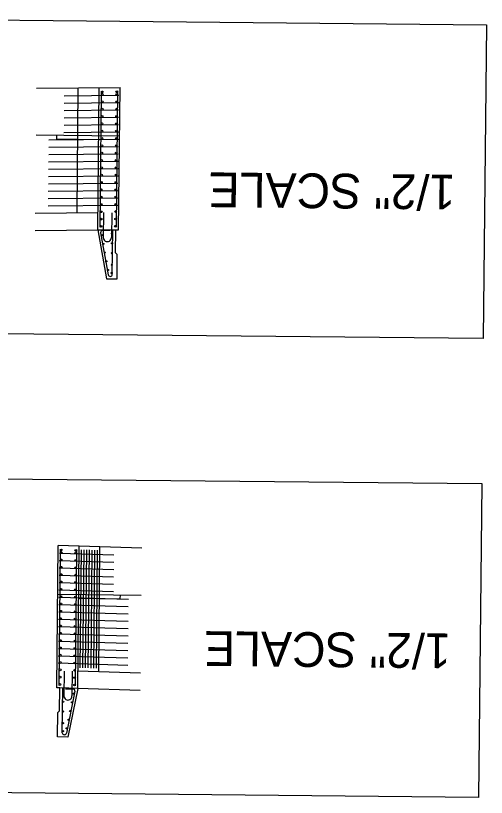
# Model space of a CAD drawing. Extents: x 631918 to 632319, y 373181 to 373282.
# Drawn here: x 631978.4 to 632012.2, y 373182.8 to 373239 of the extents above; entities that cross this region are included whole.
import ezdxf

# ---------------------------------------------------------------- set-up
doc = ezdxf.new("R2010")
doc.units = 0
for name, color, linetype in [('B_Boring', 7, 'Continuous'), ('BD-PROP-COSS', 7, 'Continuous'), ('BD-REMOVE', 7, 'Continuous'), ('R_Border_Scale', 7, 'Continuous'), ('R_Shade Removal', 7, 'Continuous')]:
    doc.layers.add(name, color=color, linetype=linetype)

msp = doc.modelspace()

# ---------------------------------------------------------------- linework, layer by layer
at = {"layer": 'B_Boring'}
for p, q in [((631984.267, 373223.578), (631984.369, 373233.817)), ((631982.822, 373190.59), (631982.924, 373200.83))]:
    msp.add_line(p, q, dxfattribs=at)
at = {"layer": 'BD-PROP-COSS'}
for p, q in [((631981.861, 373233.229), (631985.777, 373233.269)), ((631984.435, 373223.767), (631984.533, 373233.568)), ((631985.602, 373223.777), (631985.699, 373233.58)), ((631981.855, 373232.702), (631985.772, 373232.741)), ((631981.85, 373232.175), (631985.767, 373232.214)), ((631981.845, 373231.648), (631985.761, 373231.687)), ((631981.84, 373231.12), (631985.756, 373231.16)), ((631981.837, 373230.593), (631985.753, 373230.633)), ((631980.748, 373230.055), (631985.748, 373230.105)), ((631980.743, 373229.528), (631985.743, 373229.578)), ((631980.738, 373229.001), (631985.738, 373229.051)), ((631980.733, 373228.474), (631985.732, 373228.524)), ((631980.727, 373227.946), (631985.727, 373227.997)), ((631980.722, 373227.419), (631985.722, 373227.469)), ((631980.717, 373226.892), (631985.717, 373226.942)), ((631980.712, 373226.365), (631985.711, 373226.415)), ((631980.706, 373225.838), (631985.706, 373225.888)), ((631980.701, 373225.31), (631985.701, 373225.361)), ((631984.684, 373224.824), (631984.666, 373223.032)), ((631985.267, 373224.818), (631985.249, 373223.026)), ((631984.473, 373223.373), (631985.017, 373220.355)), ((631985.141, 373223.54), (631984.618, 373223.545)), ((631985.306, 373220.379), (631985.338, 373223.579)), ((631981.491, 373190.816), (631981.589, 373200.619)), ((631985.42, 373200.192), (631981.505, 373200.309)), ((631982.657, 373190.783), (631982.755, 373200.585)), ((631983.003, 373192.086), (631983.088, 373200.575)), ((631983.198, 373192.08), (631983.282, 373200.569)), ((631983.392, 373192.075), (631983.477, 373200.563)), ((631983.587, 373192.069), (631983.671, 373200.557)), ((631983.781, 373192.063), (631983.865, 373200.551)), ((631983.975, 373192.057), (631984.06, 373200.545)), ((631984.17, 373192.051), (631984.254, 373200.54)), ((631985.414, 373199.665), (631981.499, 373199.782)), ((631985.409, 373199.138), (631981.494, 373199.255)), ((631985.404, 373198.611), (631981.489, 373198.728)), ((631985.399, 373198.083), (631981.484, 373198.201)), ((631985.391, 373197.556), (631981.476, 373197.673)), ((631986.468, 373196.997), (631981.471, 373197.146)), ((631986.463, 373196.469), (631981.465, 373196.619)), ((631986.458, 373195.942), (631981.46, 373196.092)), ((631986.447, 373194.888), (631981.45, 373195.038)), ((631986.453, 373195.415), (631981.455, 373195.565)), ((631986.442, 373194.361), (631981.444, 373194.51)), ((631986.437, 373193.834), (631981.439, 373193.983)), ((631986.432, 373193.306), (631981.434, 373193.456)), ((631986.427, 373192.779), (631981.429, 373192.929)), ((631986.421, 373192.252), (631981.424, 373192.402)), ((631981.847, 373191.85), (631981.829, 373190.059)), ((631982.43, 373191.844), (631982.412, 373190.053)), ((631981.719, 373187.413), (631981.751, 373190.613)), ((631981.947, 373190.57), (631982.47, 373190.565)), ((631982.612, 373190.39), (631982.008, 373187.383))]:
    msp.add_line(p, q, dxfattribs=at)
for points in [[(632011.971, 373215.759), (631944.86, 373216.426), (631945.084, 373238.992), (632012.196, 373238.325)], [(632011.643, 373182.761), (631944.532, 373183.428), (631944.756, 373205.994), (632011.868, 373205.326)]]:
    msp.add_lwpolyline(points, close=True, dxfattribs=at)
for centre, radius in [((631984.593, 373233.318), 0.0625), ((631984.595, 373233.506), 0.0625), ((631985.634, 373233.33), 0.0625), ((631985.636, 373233.517), 0.0625), ((631984.588, 373232.791), 0.0625), ((631985.629, 373232.802), 0.0625), ((631984.582, 373232.264), 0.0625), ((631985.624, 373232.275), 0.0625), ((631984.577, 373231.737), 0.0625), ((631985.619, 373231.748), 0.0625), ((631984.572, 373231.209), 0.0625), ((631985.613, 373231.221), 0.0625), ((631984.567, 373230.682), 0.0625), ((631985.608, 373230.694), 0.0625), ((631984.561, 373230.155), 0.0625), ((631985.603, 373230.166), 0.0625), ((631984.556, 373229.628), 0.0625), ((631985.598, 373229.639), 0.0625), ((631984.551, 373229.101), 0.0625), ((631985.592, 373229.112), 0.0625), ((631984.546, 373228.573), 0.0625), ((631985.587, 373228.585), 0.0625), ((631984.54, 373228.046), 0.0625), ((631985.582, 373228.058), 0.0625), ((631984.535, 373227.519), 0.0625), ((631985.577, 373227.53), 0.0625), ((631984.525, 373226.465), 0.0625), ((631984.53, 373226.992), 0.0625), ((631985.566, 373226.476), 0.0625), ((631985.571, 373227.003), 0.0625), ((631984.519, 373225.937), 0.0625), ((631985.561, 373225.949), 0.0625), ((631984.514, 373225.41), 0.0625), ((631985.556, 373225.422), 0.0625), ((631984.509, 373224.883), 0.0625), ((631985.551, 373224.895), 0.0625), ((631984.504, 373224.356), 0.0625), ((631985.545, 373224.367), 0.0625), ((631984.499, 373223.829), 0.0625), ((631985.54, 373223.84), 0.0625), ((631984.548, 373223.2), 0.0417), ((631985.294, 373223.317), 0.0417), ((631984.661, 373222.574), 0.0417), ((631985.287, 373222.609), 0.0417), ((631984.773, 373221.948), 0.0417), ((631985.28, 373221.901), 0.0417), ((631984.886, 373221.321), 0.0417), ((631985.271, 373221.068), 0.0417), ((631984.998, 373220.695), 0.0417), ((631985.266, 373220.484), 0.0417), ((631981.649, 373200.368), 0.0625), ((631981.65, 373200.555), 0.0625), ((631982.69, 373200.335), 0.0625), ((631982.691, 373200.523), 0.0625), ((631981.643, 373199.84), 0.0625), ((631982.684, 373199.808), 0.0625), ((631981.638, 373199.313), 0.0625), ((631982.679, 373199.281), 0.0625), ((631981.633, 373198.786), 0.0625), ((631982.674, 373198.754), 0.0625), ((631981.628, 373198.259), 0.0625), ((631982.669, 373198.227), 0.0625), ((631981.617, 373197.204), 0.0625), ((631981.622, 373197.732), 0.0625), ((631982.663, 373197.699), 0.0625), ((631981.612, 373196.677), 0.0625), ((631982.653, 373196.645), 0.0625), ((631982.658, 373197.172), 0.0625), ((631981.607, 373196.15), 0.0625), ((631982.648, 373196.118), 0.0625), ((631981.601, 373195.623), 0.0625), ((631982.642, 373195.591), 0.0625), ((631981.596, 373195.096), 0.0625), ((631982.637, 373195.064), 0.0625), ((631981.591, 373194.568), 0.0625), ((631982.632, 373194.536), 0.0625), ((631981.586, 373194.041), 0.0625), ((631982.627, 373194.009), 0.0625), ((631981.58, 373193.514), 0.0625), ((631982.621, 373193.482), 0.0625), ((631981.575, 373192.987), 0.0625), ((631982.616, 373192.955), 0.0625), ((631981.57, 373192.46), 0.0625), ((631982.611, 373192.428), 0.0625), ((631981.565, 373191.933), 0.0625), ((631982.606, 373191.9), 0.0625), ((631981.559, 373191.405), 0.0625), ((631982.601, 373191.373), 0.0625), ((631981.554, 373190.878), 0.0625), ((631982.595, 373190.846), 0.0625), ((631981.79, 373190.351), 0.0417), ((631982.533, 373190.218), 0.0417), ((631981.783, 373189.642), 0.0417), ((631982.408, 373189.594), 0.0417), ((631981.776, 373188.934), 0.0417), ((631982.283, 373188.971), 0.0417), ((631982.158, 373188.347), 0.0417), ((631981.768, 373188.101), 0.0417), ((631982.034, 373187.723), 0.0417), ((631981.762, 373187.517), 0.0417)]:
    msp.add_circle(centre, radius, dxfattribs=at)
for centre, radius, start, end in [((631984.617, 373223.399), 0.146, 89.4304, 190.2146), ((631984.958, 373223.029), 0.292, 179.4304, 359.4304), ((631985.16, 373220.381), 0.146, 190.2146, 359.4304), ((631982.469, 373190.419), 0.146, 348.6461, 89.4304), ((631982.12, 373190.056), 0.292, 179.4304, 359.4304), ((631981.865, 373187.412), 0.146, 179.4304, 348.6461)]:
    msp.add_arc(centre, radius, start, end, dxfattribs=at)
at = {"layer": 'R_Border_Scale'}
for p, q in [((631982.779, 373224.813), (631982.868, 373233.802)), ((631979.778, 373224.783), (631984.279, 373224.829)), ((631984.267, 373223.578), (631985.559, 373223.591)), ((631984.334, 373191.796), (631984.423, 373200.785)), ((631987.334, 373191.706), (631982.834, 373191.841)), ((631982.822, 373190.59), (631981.531, 373190.629))]:
    msp.add_line(p, q, dxfattribs=at)
at = {"layer": 'R_Shade Removal'}
for p, q in [((631979.868, 373233.772), (631985.869, 373233.832)), ((631985.767, 373223.593), (631985.869, 373233.832)), ((631985.834, 373230.332), (631979.834, 373230.392)), ((631981.332, 373230.099), (631981.334, 373230.377)), ((631984.331, 373230.069), (631981.332, 373230.099)), ((631979.766, 373223.532), (631984.267, 373223.578)), ((631984.267, 373223.578), (631984.899, 373220.071)), ((631985.542, 373221.94), (631985.559, 373223.591)), ((631985.559, 373223.591), (631985.767, 373223.593)), ((631985.666, 373221.814), (631985.542, 373221.94)), ((631985.649, 373220.064), (631985.666, 373221.814)), ((631984.899, 373220.071), (631985.649, 373220.064)), ((631981.323, 373190.635), (631981.424, 373200.874)), ((631987.423, 373200.695), (631981.424, 373200.874)), ((631981.39, 373197.375), (631987.389, 373197.315)), ((631985.886, 373197.052), (631985.889, 373197.33)), ((631982.886, 373197.082), (631985.886, 373197.052)), ((631981.531, 373190.629), (631981.323, 373190.635)), ((631981.514, 373188.978), (631981.531, 373190.629)), ((631982.822, 373190.59), (631982.12, 373187.097)), ((631987.321, 373190.456), (631982.822, 373190.59)), ((631981.371, 373187.105), (631981.388, 373188.855)), ((631981.388, 373188.855), (631981.514, 373188.978)), ((631982.12, 373187.097), (631981.371, 373187.105))]:
    msp.add_line(p, q, dxfattribs=at)

# ---------------------------------------------------------------- texts
at = {"layer": 'BD-REMOVE'}
for p in [(632009.975, 373227.543), (632009.647, 373194.544)]:
    msp.add_text('1/2" SCALE', height=2.5, rotation=179.4304, dxfattribs=at).set_placement(p)

doc.saveas('drawing.dxf')
